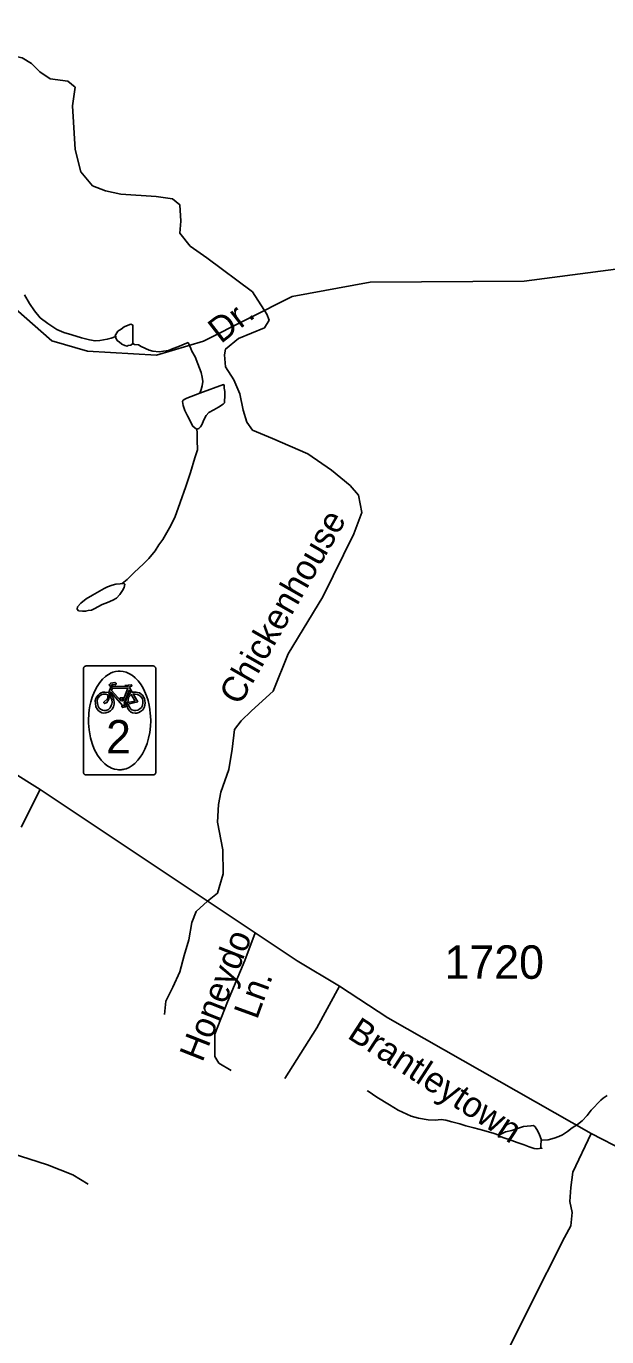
# Model space of a CAD drawing. Extents: x 2126262 to 2293712, y 749403 to 919119.
# Drawn here: x 2210024 to 2212194, y 795436 to 800334 of the extents above; entities that cross this region are included whole.
import ezdxf

# ---------------------------------------------------------------- set-up
doc = ezdxf.new("R2010")
doc.units = 0
for name, color, linetype in [('Exist Hydrographic Misc Water Feature', 7, 'Continuous'), ('Exist Road Non-System Type 51', 7, 'Continuous'), ('Exist Road Non-System Type 51 Label', 7, 'Continuous'), ('Exist Road Secondary Bike CELL', 7, 'Continuous'), ('Exist Road Secondary Type 51 Attributed', 7, 'Continuous'), ('Exist Road Secondary Type 51 Label', 7, 'Continuous'), ('Exist Road Secondary Type 51 Number Label', 7, 'Continuous')]:
    doc.layers.add(name, color=color, linetype=linetype)

msp = doc.modelspace()

# ---------------------------------------------------------------- linework, layer by layer
at = {"layer": 'Exist Hydrographic Misc Water Feature'}
for points in [[(2213880.4, 798569.4), (2213805.4, 798603.7), (2213779.4, 798686.2), (2213578.4, 798884), (2213286.4, 799040.9), (2212676.4, 799210.8), (2212568.3, 799275.4), (2212408.4, 799449.3), (2211884.5, 799381.3), (2211309.5, 799376.8), (2211018.3, 799323.8), (2210686.4, 799156.7), (2210511.5, 799104.6), (2210253.5, 799119.7), (2210119.4, 799158.5), (2209985.5, 799276.2), (2209941.4, 799582.1), (2209907.4, 799700.9), (2209832.5, 799774.6), (2209656.4, 799840.5), (2209256.5, 799904.6)], [(2210017.9, 799329.5), (2210036.2, 799297.7), (2210054.4, 799269.8), (2210076.4, 799244), (2210104.7, 799222.2), (2210138.9, 799200.4), (2210165, 799188.6), (2210194.9, 799180.8), (2210231, 799169.1), (2210260.9, 799161.3), (2210281.2, 799157.4), (2210298.9, 799159.5), (2210326.9, 799163.7), (2210340.9, 799167.8), (2210358.9, 799173.9)], [(2210358.9, 799173.9), (2210356.9, 799177.9), (2210358.9, 799181.9), (2210366.7, 799194), (2210378.6, 799202.1), (2210390.7, 799210.2), (2210404.7, 799216.2), (2210414.7, 799220.3), (2210420.7, 799218.4), (2210422.7, 799214.4), (2210423.1, 799148.4)], [(2210423.1, 799148.4), (2210415.1, 799142.4), (2210405.3, 799140.3), (2210401.2, 799138.3), (2210393.2, 799140.2), (2210381.3, 799146.1), (2210371, 799154), (2210364.9, 799158), (2210358.9, 799168), (2210358.9, 799173.9)], [(2210423.1, 799148.4), (2210429.3, 799144.4), (2210443.2, 799142.6), (2210453.3, 799136.6), (2210483.2, 799122.8), (2210497.1, 799118.9), (2210521.1, 799117.1), (2210537.1, 799119.2), (2210555.2, 799121.3), (2210567.3, 799127.4), (2210597.2, 799137.6), (2210622.8, 799149.8), (2210629, 799151.8)], [(2210672.3, 798962.2), (2210678.2, 798976.2), (2210682.1, 798990.2), (2210683.9, 799006.3), (2210681.9, 799022.2), (2210677.6, 799040.2), (2210665.5, 799072.1), (2210655.4, 799098.1), (2210643.1, 799119.9), (2210639.2, 799129.9), (2210629, 799151.8)], [(2210661.2, 798828.2), (2210669.2, 798830.2), (2210675.1, 798836.2), (2210681.3, 798846.3), (2210687, 798860.3), (2210696.9, 798878.4), (2210706.7, 798890.4), (2210724.7, 798900.6), (2210742.6, 798910.7), (2210760.4, 798920.8), (2210764.5, 798926.8), (2210764.5, 798934.8), (2210766.4, 798948.8), (2210766.2, 798968.9), (2210764.1, 798980.8), (2210763.9, 798990.8), (2210761.9, 798994.8), (2210672.3, 798962.2)], [(2210672.3, 798962.2), (2210624.5, 798943.9), (2210616.5, 798939.8), (2210610.5, 798935.8), (2210608.5, 798931.7), (2210610.7, 798915.8), (2210616.7, 798897.8), (2210626.9, 798877.9), (2210639, 798854), (2210645.2, 798840.1), (2210655.2, 798832.1), (2210661.2, 798828.2)], [(2210383.1, 798250.5), (2210401.2, 798266.5), (2210413.3, 798278.7), (2210427, 798292.7), (2210444.8, 798308.9), (2210462.7, 798325), (2210482.6, 798345.1), (2210506.4, 798373.2), (2210520.1, 798395.4), (2210534.3, 798415.4), (2210559.7, 798459.6), (2210579.4, 798497.7), (2210599.3, 798553.9), (2210620.6, 798614), (2210638.4, 798666), (2210654, 798720.2), (2210663.6, 798750.2), (2210663.4, 798786.2), (2210663.2, 798814.2), (2210661.2, 798828.2)], [(2210383.1, 798250.5), (2210389.3, 798250.5), (2210393.2, 798248.5), (2210389.5, 798236.5), (2210383.3, 798224.5), (2210373.5, 798210.4), (2210361.6, 798196.4), (2210347.7, 798188.2), (2210327.8, 798180.1), (2210307.9, 798172), (2210291.9, 798163.9), (2210280, 798157.8), (2210267.9, 798151.7), (2210256, 798149.6), (2210245.9, 798147.5), (2210233.9, 798147.4), (2210219.9, 798149.3), (2210214, 798155.3), (2210216, 798163.3), (2210227.9, 798177.4), (2210247.6, 798193.5), (2210271.6, 798207.7), (2210315.5, 798232), (2210327.4, 798238.1), (2210345.4, 798244.2), (2210359.1, 798248.3), (2210375.1, 798250.4), (2210383.1, 798250.5)], [(2211297.9, 796355.4), (2211302, 796353.4), (2211334.2, 796331.7), (2211382.1, 796302), (2211414.3, 796282.3), (2211462.7, 796260.6), (2211490.6, 796252.8), (2211526.7, 796247), (2211552.7, 796245.2), (2211574.7, 796247.4), (2211592.7, 796245.5), (2211614.7, 796239.6), (2211644.6, 796231.8), (2211666.8, 796224), (2211696.7, 796216.2), (2211734.8, 796206.5), (2211773, 796194.8), (2211790.8, 796188.9)], [(2211948.9, 796170), (2211953, 796170), (2211974.9, 796172.2), (2211996.9, 796178.3), (2212014.9, 796184.4), (2212028.9, 796190.5), (2212046.7, 796202.7), (2212064.6, 796216.8), (2212084.4, 796228.9), (2212102.5, 796243), (2212120.1, 796263.2), (2212136.1, 796283.2), (2212172, 796319.5), (2212180, 796327.6), (2212195.6, 796337.7)], [(2211790.8, 796188.9), (2211815, 796201), (2211838.6, 796207.2), (2211882.7, 796221.5), (2211910.6, 796223.7), (2211920.6, 796225.8), (2211926.6, 796219.9), (2211936.6, 796203.9), (2211943, 796190), (2211948.9, 796174), (2211948.9, 796170)], [(2211948.9, 796170), (2211948.9, 796166), (2211947.1, 796156), (2211947.1, 796144), (2211951.2, 796140), (2211933.1, 796137.9), (2211923.1, 796139.8), (2211903.2, 796145.7), (2211885.1, 796153.5), (2211859.1, 796161.4), (2211839, 796169.2), (2211829, 796173.2), (2211816.9, 796177.1), (2211808.9, 796179), (2211798.8, 796182.9), (2211789, 796182.9), (2211790.8, 796188.9)]]:
    msp.add_lwpolyline(points, dxfattribs=at)
at = {"layer": 'Exist Road Non-System Type 51'}
msp.add_line((2210076.1, 797480.8), (2210005.6, 797340.4), dxfattribs=at)
for points in [[(2210206.4, 800106.2), (2210180, 800128.2), (2210114.1, 800137), (2210074.5, 800163.4), (2210043.7, 800194.2), (2210008.6, 800216.2), (2209947, 800229.4), (2209806.4, 800264.5), (2209667.7, 800333.9)], [(2210914.1, 799206.3), (2210931.7, 799235.3), (2210922.9, 799257.3), (2210870.1, 799340.9), (2210698.7, 799468.5), (2210637.1, 799512.4), (2210597.6, 799560.8), (2210602, 799604.8), (2210597.6, 799666.4), (2210571.2, 799688.4), (2210509.7, 799697.2), (2210377.8, 799706), (2210320.7, 799719.2), (2210272.3, 799736.8), (2210228.4, 799789.5), (2210206.4, 799873.1), (2210197.6, 800035.8), (2210206.4, 800106.2)], [(2211249, 798436.4), (2211278.9, 798515.8), (2211265.7, 798581.8), (2211234.9, 798616.9), (2211164.6, 798674.1), (2211076.7, 798735.7), (2210944.8, 798792.9), (2210870.1, 798823.7), (2210848.1, 798854.5), (2210834.9, 798898.4), (2210821.8, 798960), (2210799.8, 799012.8), (2210769, 799061.2), (2210764.6, 799105.2), (2210769, 799127.1), (2210817.4, 799166.7), (2210914.1, 799206.3)], [(2210702, 797063.8), (2210738.9, 797093.4), (2210759.8, 797166), (2210758.4, 797255.4), (2210738.9, 797358.8), (2210742.4, 797425.1), (2210750.8, 797471.2), (2210781.5, 797556.4), (2210794, 797631.8), (2210802.4, 797705.9), (2210827.5, 797738), (2210866.6, 797775.7), (2210946.8, 797849), (2211002.7, 797988.7), (2211133.1, 798201.7), (2211249, 798436.4)], [(2210702, 797063.8), (2210659.3, 797024.9), (2210642.6, 796984.4), (2210631.4, 796918.8), (2210614.7, 796860.1), (2210597.9, 796800.1), (2210572.1, 796742.1), (2210545.6, 796690.4), (2210541.4, 796640.1)], [(2210880, 796945.8), (2210840.8, 796842), (2210776.6, 796686.9), (2210728.4, 796566.1), (2210728.4, 796483.7), (2210743.8, 796458.6), (2210789.8, 796430.6)], [(2209662.3, 796735.2), (2209615.5, 796666), (2209600.1, 796615.7), (2209607.1, 796593.3), (2209628, 796582.2), (2209671.3, 796585), (2209707.6, 796573.8), (2209735.5, 796554.2), (2209750.8, 796520.7), (2209782.9, 796438.3), (2209803.2, 796338.4), (2209804.6, 796292.3), (2209800.4, 796251.8), (2209811.5, 796219.7), (2209861.8, 796172.2), (2209967.9, 796121.9), (2210103.2, 796078.6), (2210198.1, 796040.9), (2210255.3, 796006)], [(2211195.4, 796746.1), (2211110.1, 796590.6), (2210990.1, 796400.6)], [(2212135.3, 796195.1), (2212067.5, 796050.6), (2212059.1, 795993.3), (2212056.3, 795941.6), (2212064.7, 795899.7), (2212059.1, 795850.9), (2212035.4, 795806.2), (2211904.9, 795547.1), (2211764, 795264.9), (2211636.3, 794997.4)]]:
    msp.add_lwpolyline(points, dxfattribs=at)
at = {"layer": 'Exist Road Secondary Bike CELL'}
for points in [[(2210247.5, 797942.8), (2210248.4, 797942.9), (2210281.4, 797942.9), (2210464.8, 797942.9), (2210497.8, 797942.9), (2210499, 797942.8), (2210499.6, 797942.7), (2210500.4, 797942.5), (2210501.1, 797942.3), (2210501.8, 797942), (2210503.1, 797941.4), (2210503.7, 797941), (2210504.4, 797940.6), (2210505.1, 797939.9), (2210506, 797938.9), (2210506.6, 797938.1), (2210506.9, 797937.7), (2210507.1, 797937.3), (2210507.4, 797936.8), (2210507.6, 797936.4), (2210507.8, 797935.9), (2210508, 797935.2), (2210508.3, 797934.2), (2210508.4, 797933.3), (2210508.5, 797933), (2210508.5, 797932.6), (2210508.5, 797899.1), (2210508.5, 797579.2), (2210508.5, 797546.2), (2210508.4, 797545), (2210508.3, 797544.3), (2210508.2, 797543.6), (2210508, 797542.9), (2210507.7, 797542.2), (2210507, 797540.8), (2210506.6, 797540.2), (2210506.2, 797539.6), (2210505.6, 797538.9), (2210505.1, 797538.4), (2210504.6, 797537.9), (2210504.2, 797537.7), (2210503.8, 797537.3), (2210503.3, 797537), (2210503, 797536.8), (2210502.5, 797536.6), (2210501.6, 797536.2), (2210500.8, 797535.9), (2210499.9, 797535.7), (2210499.5, 797535.6), (2210499, 797535.5), (2210498.6, 797535.5), (2210498.2, 797535.4), (2210497.7, 797535.4), (2210464.7, 797535.4), (2210281.4, 797535.4), (2210248.4, 797535.4), (2210247.8, 797535.5), (2210247.2, 797535.5), (2210246.6, 797535.6), (2210245.8, 797535.8), (2210245.1, 797536), (2210244.4, 797536.2), (2210243.7, 797536.6), (2210243.1, 797536.9), (2210242.4, 797537.3), (2210241.8, 797537.7), (2210241.5, 797538), (2210241.1, 797538.3), (2210240.8, 797538.6), (2210240.5, 797539.1), (2210240.1, 797539.5), (2210239.7, 797539.9), (2210239.4, 797540.4), (2210239.2, 797540.8), (2210238.9, 797541.3), (2210238.6, 797541.9), (2210238.4, 797542.4), (2210238.3, 797542.7), (2210238.2, 797543), (2210238.1, 797543.2), (2210238, 797543.5), (2210238, 797543.7), (2210237.9, 797543.9), (2210237.9, 797544.2), (2210237.8, 797544.4), (2210237.8, 797544.7), (2210237.8, 797544.9), (2210237.7, 797545.1), (2210237.7, 797545.4), (2210237.7, 797546), (2210237.6, 797579.2), (2210237.6, 797899.1), (2210237.7, 797932.1), (2210237.8, 797933.3), (2210237.9, 797934), (2210238, 797934.7), (2210238.2, 797935.5), (2210238.5, 797936.2), (2210239.1, 797937.5), (2210239.5, 797938.1), (2210240, 797938.7), (2210240.6, 797939.4), (2210241.6, 797940.4), (2210242.4, 797941), (2210242.8, 797941.3), (2210243.2, 797941.5), (2210243.7, 797941.7), (2210244.1, 797941.9), (2210244.6, 797942.1), (2210245.4, 797942.4), (2210246.3, 797942.6), (2210247.2, 797942.8)], [(2210373, 797554.9), (2210368.4, 797555.1), (2210364, 797555.5), (2210354, 797557.2), (2210342.8, 797561.3), (2210336.3, 797564.5), (2210331, 797567.5), (2210325.3, 797571.4), (2210317.3, 797577.3), (2210303.6, 797591.2), (2210290.1, 797609.2), (2210278.3, 797632.3), (2210270, 797653.2), (2210264.8, 797673.6), (2210259.1, 797704.5), (2210257.3, 797728.8), (2210257.1, 797740.7), (2210257.3, 797749.4), (2210257.6, 797755.6), (2210258.3, 797764.9), (2210259.7, 797779.2), (2210262.3, 797793.8), (2210264.4, 797803.3), (2210265.7, 797808.5), (2210268.4, 797818.1), (2210270.9, 797826.6), (2210278.8, 797847.1), (2210288.6, 797865.6), (2210299.5, 797881.3), (2210309, 797893), (2210320.5, 797903.8), (2210329.4, 797909.8), (2210334, 797912.5), (2210339.3, 797915.3), (2210347.9, 797919.3), (2210358.2, 797921.9), (2210367.6, 797923.4), (2210375.2, 797923.6), (2210386.1, 797922.4), (2210397.5, 797919.3), (2210410.5, 797913.7), (2210421.8, 797906.8), (2210431.5, 797898.5), (2210442.2, 797887.5), (2210450.9, 797876.1), (2210459.5, 797862.2), (2210466.6, 797848.6), (2210473.7, 797831.4), (2210479.3, 797813.3), (2210483.3, 797796.3), (2210486.3, 797779.7), (2210487.8, 797765.1), (2210488.4, 797757), (2210489.3, 797738), (2210488.4, 797717.7), (2210485.7, 797694.1), (2210481.4, 797673.4), (2210475.6, 797652.5), (2210467.8, 797632.4), (2210458.7, 797614.8), (2210450.1, 797601.7), (2210441.3, 797590.2), (2210430, 797578.5), (2210419.7, 797570.2), (2210408.4, 797563.7), (2210397, 797558.8), (2210389.9, 797556.9), (2210385.8, 797556.2), (2210382.3, 797555.5), (2210378.4, 797555.2)], [(2210392.5, 797869.6), (2210416.6, 797872.5), (2210418.4, 797870.7), (2210417, 797866.9), (2210411.1, 797865.1), (2210409.5, 797861.9), (2210419.6, 797844.7), (2210434.1, 797845.4), (2210446.9, 797842.5), (2210458.2, 797834), (2210463.5, 797825.4), (2210466.1, 797820.8), (2210467.9, 797813), (2210468.3, 797804.8), (2210467.3, 797796.3), (2210465.5, 797789.8), (2210461.9, 797782.9), (2210458.4, 797777.8), (2210451.6, 797772.3), (2210445.5, 797768.7), (2210437.1, 797766.7), (2210431.8, 797766.4), (2210421, 797768.1), (2210414.2, 797771.6), (2210410.8, 797774.5), (2210405.6, 797780.9), (2210402.2, 797787), (2210397.6, 797799.2), (2210396.5, 797805.1), (2210403.9, 797799.8), (2210409.8, 797789.9), (2210413.9, 797783.2), (2210419.2, 797779.4), (2210427.4, 797776.1), (2210433.5, 797775.9), (2210441.6, 797777.8), (2210449.2, 797782), (2210454.6, 797787.3), (2210458.9, 797794.5), (2210460.3, 797804.5), (2210460, 797812.7), (2210458.2, 797819.4), (2210454.7, 797825.5), (2210451.1, 797829.8), (2210445.1, 797834.3), (2210439.4, 797836.1), (2210430.1, 797837.9), (2210423.6, 797838.6), (2210441.1, 797809), (2210403.9, 797799.8), (2210396.5, 797805.1), (2210430.8, 797811.3), (2210416.5, 797835.7), (2210406.7, 797825.1), (2210403.8, 797806.6), (2210396.5, 797805.1), (2210396.9, 797812.9), (2210400, 797824.7), (2210405.5, 797832.9), (2210413.3, 797841.8), (2210408.3, 797852.3), (2210389.5, 797804.4), (2210396.7, 797805.2), (2210397.6, 797799.2), (2210389.2, 797798.2), (2210391, 797793), (2210396, 797790.3), (2210383.5, 797787.5), (2210380.3, 797791.4), (2210384.9, 797793.8), (2210340.2, 797844.9), (2210338.5, 797840), (2210344.7, 797831.7), (2210348.9, 797823.7), (2210351.6, 797815.1), (2210353, 797807.7), (2210352.2, 797800.2), (2210350.2, 797790.3), (2210345.2, 797781.4), (2210338.4, 797774.6), (2210330.6, 797769.9), (2210321, 797767.5), (2210314, 797766.9), (2210306.9, 797767.8), (2210294.6, 797775.4), (2210290.6, 797779.9), (2210284.8, 797790.3), (2210282.4, 797803.2), (2210282.3, 797812.4), (2210284.6, 797820.6), (2210288.2, 797827.9), (2210292.4, 797833.2), (2210298.5, 797839.2), (2210303.8, 797842.5), (2210310.6, 797844.6), (2210317.6, 797845.3), (2210332.9, 797843.6), (2210336.4, 797835.4), (2210331.8, 797816.4), (2210325.7, 797806.5), (2210316.9, 797802.3), (2210313.4, 797805.8), (2210327.6, 797820.3), (2210330.7, 797834.1), (2210327.5, 797835.5), (2210321.5, 797837.4), (2210311.9, 797837.7), (2210306.5, 797836), (2210299.1, 797831.7), (2210292, 797822.4), (2210288.9, 797812.7), (2210290.2, 797802.1), (2210292.9, 797792.1), (2210296.4, 797785.7), (2210301.4, 797781.7), (2210308.7, 797777.2), (2210315.2, 797776.1), (2210323.2, 797776.6), (2210331, 797780), (2210337.7, 797786.7), (2210342, 797794.9), (2210344.5, 797800.6), (2210345.1, 797808), (2210344.1, 797815.9), (2210340.3, 797825), (2210332.9, 797843.6), (2210340.6, 797865.3), (2210346, 797859.6), (2210343, 797851.1), (2210378.7, 797811.3), (2210377.6, 797816.3), (2210373.9, 797822.7), (2210375.6, 797824.1), (2210385.8, 797824.1), (2210383.8, 797816.8), (2210384.9, 797811.6), (2210403.8, 797859.3), (2210346, 797859.6), (2210340.6, 797865.3), (2210334, 797872.4), (2210339.7, 797879.1), (2210354.9, 797881.1), (2210361, 797876.3), (2210357.8, 797872), (2210348.5, 797873.1), (2210342.1, 797871.6), (2210343.5, 797870.3), (2210346.8, 797870.3), (2210345.4, 797867.1), (2210404.6, 797866.6), (2210405, 797868)]]:
    msp.add_lwpolyline(points, close=True, dxfattribs=at)
at = {"layer": 'Exist Road Secondary Type 51 Attributed'}
msp.add_lwpolyline([(2215479.3, 795107.4), (2214934, 795234.8), (2214110, 795457.6), (2213948.1, 795509.3), (2213819.7, 795541.4), (2213419.9, 795659.4), (2213223.1, 795723.7), (2212631.4, 795949.9), (2212513.5, 796000.9), (2212135.3, 796195.1), (2211375.4, 796627.4), (2211195.4, 796746.1), (2211036.3, 796841.1), (2210076.1, 797480.8), (2209962.4, 797552.7), (2209568.1, 797792.3), (2209389.5, 797892.8), (2209286.9, 797956.2)], dxfattribs=at)

# ---------------------------------------------------------------- texts
at = {"layer": 'Exist Road Non-System Type 51 Label'}
for s, rotation, p in [('Dr.', 37.9027, (2210751.5, 799145.2)), ('Chickenhouse', 60.197, (2210822.5, 797791.7)), ('Honeydo', 68.4628, (2210682.3, 796458.7)), ('Ln.', 70.0212, (2210886.7, 796618.3))]:
    msp.add_text(s, height=95, rotation=rotation, dxfattribs=at).set_placement(p)
at = {"layer": 'Exist Road Secondary Bike CELL'}
msp.add_text('2', height=125, dxfattribs=at).set_placement((2210322.5, 797615.7))
at = {"layer": 'Exist Road Secondary Type 51 Label'}
msp.add_text('Brantleytown', height=95, rotation=327.0379, dxfattribs=at).set_placement((2211220, 796554.9))
at = {"layer": 'Exist Road Secondary Type 51 Number Label'}
msp.add_text('1720', height=125, dxfattribs=at).set_placement((2211587.3, 796773.5))

doc.saveas('drawing.dxf')
